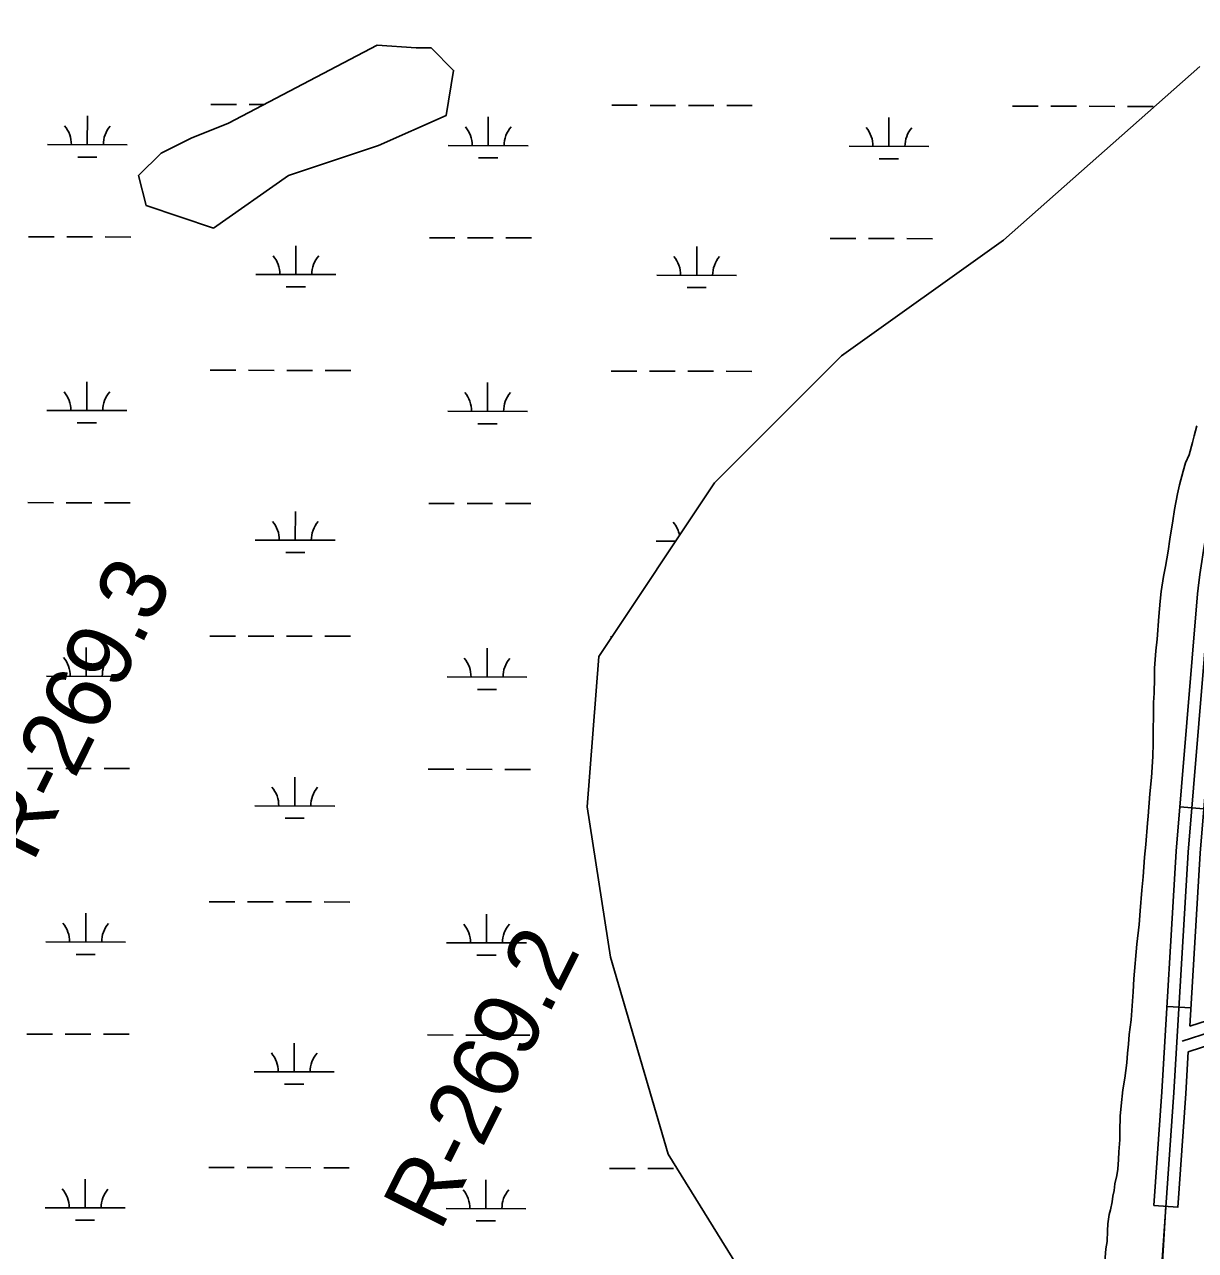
# Model space of a CAD drawing. Extents: x 3219052 to 3256913, y 800770 to 826146.
# Drawn here: x 3239192 to 3240658, y 815962 to 817496 of the extents above; entities that cross this region are included whole.
import ezdxf

# ---------------------------------------------------------------- set-up
doc = ezdxf.new("R2010")
doc.units = 0
for name, color, linetype in [('V-RIVR-RANG-IDEN', 7, 'Continuous'), ('V-ROAD-CNTR', 7, 'Continuous'), ('V-SITE-VEGE', 7, 'Continuous'), ('V-WETL-SWMP', 7, 'Continuous')]:
    doc.layers.add(name, color=color, linetype=linetype)

msp = doc.modelspace()

# ---------------------------------------------------------------- linework, layer by layer
at = {"layer": 'V-ROAD-CNTR'}
for p, q in [((3240668.9, 816514.5), (3240639, 816516.9)), ((3240652.7, 816265.3), (3240622.8, 816267.1)), ((3240636.4, 816015.7), (3240606.4, 816017.8))]:
    msp.add_line(p, q, dxfattribs=at)
for points in [[(3245577.1, 818698.4), (3245238.8, 818529.7), (3244651.8, 818233.9), (3244050.9, 817929.7), (3243594, 817700.1), (3242969.1, 817384.2), (3242177.5, 816985), (3241528.2, 816651.4), (3240737.5, 816256.9), (3240705.3, 816243.8), (3240678, 816235.2), (3240641.8, 816223.6)], [(3240649.4, 816210.3), (3240682.5, 816220.9), (3240710.4, 816229.7), (3240743.6, 816243.3), (3241535, 816638), (3242184.3, 816971.6), (3242975.9, 817370.8), (3243600.7, 817686.7), (3244057.7, 817916.4), (3244658.6, 818220.6), (3245245.5, 818516.3), (3245583.8, 818684.9)], [(3240651.3, 816242.4), (3240673.4, 816249.5), (3240700.2, 816257.9), (3240731.3, 816270.6), (3241521.4, 816664.8), (3242170.7, 816998.3), (3242962.4, 817397.6), (3243577.9, 817708.8)], [(3240703.4, 817026.2), (3240700.8, 817005.8), (3240697.7, 816985.5), (3240694.3, 816965.3), (3240690.5, 816945), (3240686.3, 816924.8), (3240685.8, 816922.4), (3240681.9, 816906.5), (3240678.2, 816890.1), (3240674.8, 816873.8), (3240671.6, 816857.2), (3240668.7, 816840.6), (3240666.2, 816824.1), (3240663.8, 816807.5), (3240661.8, 816790.8), (3240661.1, 816783.6), (3240634.4, 816461.2), (3240616.3, 816160.1), (3240606.4, 816018)], [(3240733.1, 817022.6), (3240730.5, 817001.6), (3240727.3, 816980.8), (3240723.8, 816960.1), (3240719.9, 816939.3), (3240715.7, 816918.9), (3240715.1, 816915.8), (3240711.1, 816899.6), (3240707.5, 816883.8), (3240704.2, 816867.9), (3240701.1, 816851.8), (3240698.3, 816835.8), (3240695.9, 816819.8), (3240693.6, 816803.6), (3240691.6, 816787.5), (3240691, 816780.8), (3240664.3, 816459), (3240651.3, 816242.4)], [(3240676, 816782.2), (3240649.3, 816460.1), (3240631.3, 816159.1), (3240601.3, 815728.7)], [(3240649.4, 816210.3), (3240646.3, 816158.2), (3240636.3, 816015.4)], [(3240621.3, 816017.6), (3240603.4, 815715.9), (3240587.3, 815593.5), (3240487, 815198.4), (3240481.1, 815068.4), (3240490.4, 815003.8)]]:
    msp.add_lwpolyline(points, dxfattribs=at)
at = {"layer": 'V-SITE-VEGE'}
msp.add_lwpolyline([(3239428.9, 817241.3), (3239522.8, 817307.1), (3239635.5, 817344.6), (3239720, 817382.2), (3239729.4, 817438.6), (3239701.3, 817466.8), (3239682.5, 817466.8), (3239633.7, 817470.3), (3239447.7, 817372.8), (3239400.7, 817354), (3239363.2, 817335.2), (3239335, 817307.1), (3239344.4, 817269.5)], close=True, dxfattribs=at)
msp.add_lwpolyline([(3240544.6, 815941.8), (3240546.1, 815963.5), (3240547.7, 815972.6), (3240548.2, 815986.2), (3240548.8, 815994.8), (3240550.3, 816006.4), (3240551.8, 816012.5), (3240553.9, 816022.6), (3240554.9, 816029.7), (3240556.5, 816036.7), (3240557.5, 816044.8), (3240560, 816055.4), (3240561.1, 816063.5), (3240562.1, 816075.6), (3240562.6, 816085.2), (3240563.7, 816099.9), (3240563.7, 816111), (3240564.3, 816129.7), (3240565.3, 816142.8), (3240567.4, 816162.5), (3240570, 816177.2), (3240572.6, 816196.4), (3240573.1, 816208.5), (3240574.6, 816219.6), (3240575.2, 816231.7), (3240577.8, 816250.4), (3240580.4, 816285.3), (3240581.4, 816301.4), (3240585.1, 816344.9), (3240587.7, 816369.6), (3240589.3, 816386.8), (3240591.4, 816412.6), (3240592.9, 816429.3), (3240594.5, 816454), (3240596.1, 816469.7), (3240598.2, 816496.5), (3240599.2, 816505), (3240601.3, 816533.3), (3240603.4, 816553.5), (3240605, 816579.8), (3240605.5, 816596.5), (3240605.7, 816647.5), (3240606.7, 816659.1), (3240607.3, 816677.8), (3240607.3, 816690.5), (3240608.9, 816712.2), (3240610.4, 816726.8), (3240612.5, 816755.1), (3240614.1, 816774.3), (3240615.6, 816786.5), (3240618.2, 816805.1), (3240620.8, 816817.8), (3240624.4, 816837), (3240626.4, 816852.1), (3240630, 816874.8), (3240632.1, 816889), (3240635.7, 816908.7), (3240638.3, 816919.8), (3240642.8, 816937), (3240645.9, 816947.6), (3240650.5, 816957.7), (3240654.6, 816972.8), (3240656.6, 816981.4), (3240660.2, 816994)], dxfattribs=at)
at = {"layer": 'V-WETL-SWMP'}
for p, q in [((3239447.7, 817372.8), (3239633.7, 817470.3)), ((3239633.7, 817470.3), (3239682.5, 817466.8)), ((3239682.5, 817466.8), (3239701.3, 817466.8)), ((3239701.3, 817466.8), (3239729.4, 817438.6)), ((3239729.4, 817438.6), (3239720, 817382.2)), ((3240417.8, 817226.4), (3240663.8, 817443.7)), ((3239425.4, 817396.1), (3239457.4, 817396)), ((3239473.4, 817396), (3239491.8, 817395.9)), ((3239927.4, 817395), (3239959.4, 817395)), ((3239975.4, 817394.9), (3240007.4, 817394.9)), ((3240023.4, 817394.8), (3240055.4, 817394.8)), ((3240071.4, 817394.7), (3240103.4, 817394.7)), ((3240429.3, 817394), (3240461.3, 817393.9)), ((3240477.3, 817393.9), (3240509.3, 817393.8)), ((3240525.3, 817393.8), (3240557.3, 817393.7)), ((3240573.3, 817393.7), (3240605.3, 817393.6)), ((3239270.7, 817345.7), (3239270.8, 817381.7)), ((3239720, 817382.2), (3239635.5, 817344.6)), ((3239772.7, 817344.6), (3239772.7, 817380.6)), ((3240274.6, 817343.6), (3240274.6, 817379.6)), ((3239400.7, 817354), (3239447.7, 817372.8)), ((3239220.7, 817345.8), (3239320.7, 817345.6)), ((3239363.2, 817335.2), (3239400.7, 817354)), ((3239635.5, 817344.6), (3239522.8, 817307)), ((3239722.7, 817344.7), (3239822.7, 817344.5)), ((3240224.6, 817343.7), (3240324.6, 817343.5)), ((3239258.7, 817330.3), (3239282.7, 817330.2)), ((3239335, 817307), (3239363.2, 817335.2)), ((3239760.6, 817329.2), (3239784.6, 817329.2)), ((3240262.5, 817328.2), (3240286.5, 817328.1)), ((3239344.4, 817269.5), (3239335, 817307)), ((3239522.8, 817307), (3239428.9, 817241.3)), ((3239428.9, 817241.3), (3239344.4, 817269.5)), ((3239197.1, 817230.4), (3239229.1, 817230.3)), ((3239245.1, 817230.3), (3239277.1, 817230.2)), ((3239293.1, 817230.2), (3239325.1, 817230.1)), ((3239699, 817229.3), (3239731, 817229.3)), ((3239747, 817229.2), (3239779, 817229.2)), ((3239795, 817229.1), (3239827, 817229.1)), ((3240200.9, 817228.3), (3240232.9, 817228.2)), ((3240215.2, 817081.6), (3240417.8, 817226.4)), ((3240248.9, 817228.2), (3240280.9, 817228.1)), ((3240296.9, 817228.1), (3240328.9, 817228)), ((3239531.8, 817183.3), (3239531.9, 817219.3)), ((3240033.8, 817182.2), (3240033.8, 817218.2)), ((3239481.8, 817183.4), (3239581.8, 817183.2)), ((3239983.8, 817182.3), (3240083.8, 817182.1)), ((3239519.8, 817167.9), (3239543.8, 817167.8)), ((3240021.7, 817166.8), (3240045.7, 817166.8)), ((3240056, 816922.3), (3240215.2, 817081.6)), ((3239424.7, 817063.4), (3239456.7, 817063.3)), ((3239472.7, 817063.3), (3239504.7, 817063.2)), ((3239520.7, 817063.2), (3239552.7, 817063.1)), ((3239568.7, 817063.1), (3239600.7, 817063)), ((3239926.7, 817062.4), (3239958.7, 817062.3)), ((3239974.7, 817062.3), (3240006.7, 817062.2)), ((3240022.7, 817062.2), (3240054.7, 817062.1)), ((3240070.7, 817062.1), (3240102.7, 817062)), ((3239270.1, 817013), (3239270.1, 817049)), ((3239772, 817011.9), (3239772, 817047.9)), ((3239220.1, 817013.1), (3239320.1, 817012.9)), ((3239722, 817012), (3239822, 817011.8)), ((3239258, 816997.6), (3239282, 816997.5)), ((3239759.9, 816996.5), (3239783.9, 816996.5)), ((3239911.3, 816705.1), (3240056, 816922.3)), ((3239196.4, 816897.7), (3239228.4, 816897.6)), ((3239244.4, 816897.6), (3239276.4, 816897.5)), ((3239292.4, 816897.5), (3239324.4, 816897.4)), ((3239531.1, 816850.6), (3239531.2, 816886.6)), ((3239698.3, 816896.7), (3239730.3, 816896.6)), ((3239746.3, 816896.6), (3239778.3, 816896.5)), ((3239794.3, 816896.5), (3239826.3, 816896.4)), ((3239481.1, 816850.7), (3239581.1, 816850.5)), ((3239983.1, 816849.6), (3240007.6, 816849.6)), ((3239519.1, 816835.2), (3239543.1, 816835.1)), ((3239424.1, 816730.7), (3239456.1, 816730.7)), ((3239472.1, 816730.6), (3239504.1, 816730.6)), ((3239520.1, 816730.5), (3239552.1, 816730.5)), ((3239568.1, 816730.4), (3239600.1, 816730.4)), ((3239926, 816729.7), (3239927.7, 816729.7)), ((3239269.4, 816680.3), (3239269.4, 816716.3)), ((3239771.3, 816679.3), (3239771.3, 816715.3)), ((3239896.8, 816516.8), (3239911.3, 816705.1)), ((3239219.4, 816680.4), (3239319.4, 816680.2)), ((3239721.3, 816679.4), (3239821.3, 816679.2)), ((3239257.3, 816664.9), (3239281.3, 816664.9)), ((3239759.2, 816663.9), (3239783.2, 816663.8)), ((3239195.7, 816565), (3239227.7, 816565)), ((3239243.7, 816564.9), (3239275.7, 816564.9)), ((3239291.7, 816564.8), (3239323.7, 816564.8)), ((3239697.6, 816564), (3239729.6, 816563.9)), ((3239745.6, 816563.9), (3239777.6, 816563.8)), ((3239793.6, 816563.8), (3239825.6, 816563.7)), ((3239530.5, 816517.9), (3239530.5, 816553.9)), ((3239480.5, 816518), (3239580.5, 816517.8)), ((3239925.8, 816328.5), (3239896.8, 816516.8)), ((3239518.4, 816502.5), (3239542.4, 816502.5)), ((3239423.4, 816398.1), (3239455.4, 816398)), ((3239471.4, 816398), (3239503.4, 816397.9)), ((3239519.4, 816397.9), (3239551.4, 816397.8)), ((3239567.4, 816397.8), (3239599.4, 816397.7)), ((3239268.7, 816347.6), (3239268.7, 816383.6)), ((3239770.6, 816346.6), (3239770.6, 816382.6)), ((3239218.7, 816347.8), (3239318.7, 816347.5)), ((3239720.6, 816346.7), (3239820.6, 816346.5)), ((3239256.6, 816332.2), (3239280.6, 816332.2)), ((3239758.5, 816331.2), (3239782.5, 816331.1)), ((3239998.1, 816082.3), (3239925.8, 816328.5)), ((3239195, 816232.4), (3239227, 816232.3)), ((3239243, 816232.3), (3239275, 816232.2)), ((3239291, 816232.2), (3239323, 816232.1)), ((3239696.9, 816231.3), (3239728.9, 816231.2)), ((3239744.9, 816231.2), (3239776.9, 816231.1)), ((3239792.9, 816231.1), (3239824.9, 816231)), ((3239529.8, 816185.2), (3239529.8, 816221.2)), ((3239479.8, 816185.3), (3239579.8, 816185.1)), ((3239517.7, 816169.8), (3239541.7, 816169.8)), ((3240186.2, 815778.1), (3239998.1, 816082.3)), ((3239422.7, 816065.4), (3239454.7, 816065.3)), ((3239470.7, 816065.3), (3239502.7, 816065.2)), ((3239518.7, 816065.2), (3239550.7, 816065.1)), ((3239566.7, 816065.1), (3239598.7, 816065)), ((3239924.6, 816064.3), (3239956.6, 816064.3)), ((3239972.6, 816064.2), (3240004.6, 816064.2)), ((3239268, 816015), (3239268, 816051)), ((3239769.9, 816013.9), (3239769.9, 816049.9)), ((3239218, 816015.1), (3239318, 816014.9)), ((3239719.9, 816014), (3239819.9, 816013.8)), ((3239255.9, 815999.6), (3239279.9, 815999.5)), ((3239757.8, 815998.5), (3239781.8, 815998.5))]:
    msp.add_line(p, q, dxfattribs=at)
for centre, start, end in [((3239215.5, 817346.3), 359.1081, 40.6518), ((3239326, 817346), 139.1081, 180.6517), ((3239717.4, 817345.2), 359.1081, 40.6518), ((3239827.9, 817345), 139.1081, 180.6517), ((3240219.3, 817344.2), 359.1081, 40.6518), ((3240329.8, 817343.9), 139.1081, 180.6517), ((3239476.6, 817183.8), 359.1081, 40.6518), ((3239587.1, 817183.6), 139.1081, 180.6517), ((3239978.5, 817182.8), 359.1081, 40.6518), ((3240089, 817182.6), 139.1081, 180.6517), ((3239214.8, 817013.6), 359.1081, 40.6518), ((3239325.3, 817013.4), 139.1081, 180.6517), ((3239716.7, 817012.5), 359.1081, 40.6518), ((3239827.2, 817012.3), 139.1081, 180.6517), ((3239475.9, 816851.2), 359.1081, 40.6518), ((3239586.4, 816850.9), 139.1081, 180.6517), ((3239977.8, 816850.1), 11.0299, 40.6518), ((3239214.1, 816680.9), 359.1081, 40.6518), ((3239324.6, 816680.7), 139.1081, 180.6517), ((3239716, 816679.9), 359.1081, 40.6518), ((3239826.5, 816679.6), 139.1081, 180.6517), ((3239475.2, 816518.5), 359.1081, 40.6518), ((3239585.7, 816518.3), 139.1081, 180.6517), ((3239213.4, 816348.2), 359.1081, 40.6518), ((3239323.9, 816348), 139.1081, 180.6517), ((3239715.3, 816347.2), 359.1081, 40.6518), ((3239825.8, 816347), 139.1081, 180.6517), ((3239474.5, 816185.8), 359.1081, 40.6518), ((3239585, 816185.6), 139.1081, 180.6517), ((3239212.7, 816015.6), 359.1081, 40.6518), ((3239323.2, 816015.3), 139.1081, 180.6517), ((3239714.6, 816014.5), 359.1081, 40.6518), ((3239825.1, 816014.3), 139.1081, 180.6517)]:
    msp.add_arc(centre, 35.2, start, end, dxfattribs=at)

# ---------------------------------------------------------------- texts
at = {"layer": 'V-RIVR-RANG-IDEN'}
for s, rotation, p in [('R-269.3', 63.4937, (3239202.4, 816445.8)), ('R-269.2', 63.435, (3239712.5, 815983.8))]:
    msp.add_text(s, height=83, rotation=rotation, dxfattribs=at).set_placement(p)

doc.saveas('drawing.dxf')
